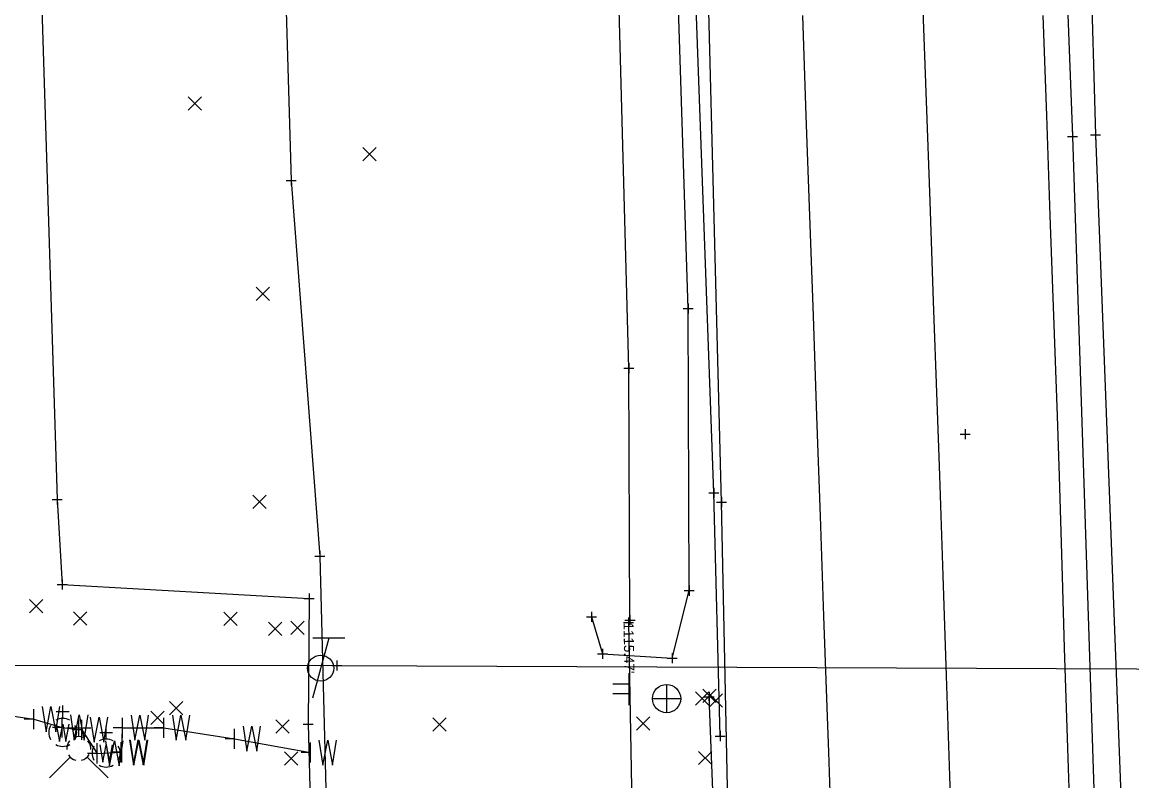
# Model space of a CAD drawing. Extents: x 146022 to 147632, y 437624 to 440659.
# Drawn here: x 146857.8 to 146968.6, y 438654.2 to 438729.9 of the extents above; entities that cross this region are included whole.
import ezdxf

# ---------------------------------------------------------------- set-up
doc = ezdxf.new("R2010")
doc.units = 0
for name, color, linetype in [('_CIVIL_CONSTRUCTION', 7, 'Continuous'), ('BR_P_Rail_Object', 7, 'Continuous'), ('DR_Channel', 7, 'Continuous'), ('DR_P_Underdrain', 7, 'Continuous'), ('DR_X_Storm_Sewer', 7, 'Continuous'), ('DT_X_Break_Line', 7, 'Continuous'), ('GE_P_Alignment_100_Distances', 7, 'Continuous'), ('PF_X_Ground_Line', 7, 'Continuous'), ('PV_P_Curb', 7, 'Continuous'), ('RD_P_Anchor_Assembly', 7, 'Continuous'), ('RD_P_Fence', 7, 'Continuous'), ('RD_P_GR_Lt_Replaced', 7, 'Continuous'), ('RD_P_GR_Rt', 7, 'Continuous'), ('SC_Scratch1', 7, 'Continuous'), ('SC_Scratch3', 7, 'Continuous'), ('SV_X_Control_Cells_Found', 7, 'Continuous'), ('UT_X_Overhead_Cable_TV', 7, 'Continuous'), ('UT_X_Overhead_Electric', 7, 'Continuous'), ('UT_X_Water', 7, 'Continuous')]:
    doc.layers.add(name, color=color, linetype=linetype)

msp = doc.modelspace()

# ---------------------------------------------------------------- linework, layer by layer
at = {"layer": '_CIVIL_CONSTRUCTION'}
for p, q in [((146874.38, 438721.14), (146875.71, 438722.48)), ((146874.38, 438722.48), (146875.71, 438721.14)), ((146891.83, 438716.1), (146893.16, 438717.43)), ((146891.83, 438717.43), (146893.16, 438716.1)), ((146881.16, 438702.15), (146882.49, 438703.48)), ((146881.16, 438703.48), (146882.49, 438702.15)), ((146880.84, 438681.37), (146882.18, 438682.7)), ((146880.84, 438682.7), (146882.18, 438681.37)), ((146858.55, 438670.97), (146859.88, 438672.31)), ((146858.55, 438672.31), (146859.88, 438670.97)), ((146862.93, 438669.75), (146864.26, 438671.08)), ((146862.93, 438671.08), (146864.26, 438669.75)), ((146877.93, 438669.69), (146879.27, 438671.02)), ((146877.93, 438671.02), (146879.27, 438669.69)), ((146882.42, 438668.71), (146883.75, 438670.05)), ((146882.42, 438670.05), (146883.75, 438668.71)), ((146884.64, 438668.79), (146885.97, 438670.13)), ((146884.64, 438670.13), (146885.97, 438668.79)), ((146925.01, 438661.74), (146926.34, 438663.08)), ((146925.01, 438663.08), (146926.34, 438661.74)), ((146925.74, 438662.02), (146927.08, 438663.36)), ((146925.74, 438663.36), (146927.08, 438662.02)), ((146872.51, 438660.77), (146873.84, 438662.11)), ((146872.51, 438662.11), (146873.84, 438660.77)), ((146926.37, 438661.54), (146927.71, 438662.87)), ((146926.37, 438662.87), (146927.71, 438661.54)), ((146870.67, 438659.82), (146872, 438661.15)), ((146870.67, 438661.15), (146872, 438659.82)), ((146883.15, 438658.97), (146884.48, 438660.3)), ((146883.15, 438660.3), (146884.48, 438658.97)), ((146898.81, 438659.14), (146900.15, 438660.47)), ((146898.81, 438660.47), (146900.15, 438659.14)), ((146919.12, 438659.24), (146920.46, 438660.58)), ((146919.12, 438660.58), (146920.46, 438659.24)), ((146884, 438655.76), (146885.33, 438657.09)), ((146884, 438657.09), (146885.33, 438655.76)), ((146925.32, 438655.81), (146926.65, 438657.14)), ((146925.32, 438657.14), (146926.65, 438655.81))]:
    msp.add_line(p, q, dxfattribs=at)
at = {"layer": 'BR_P_Rail_Object'}
msp.add_line((146857.9, 438790.96), (146861.31, 438682.29), dxfattribs=at)
msp.add_lwpolyline([(146861.31, 438682.29), (146861.8, 438673.8), (146886.47, 438672.39), (146886.37, 438659.85), (146886.65, 438648.5)], dxfattribs=at)
at = {"layer": 'DR_Channel'}
msp.add_lwpolyline([(146927.49, 438658.64), (146926.86, 438682.94), (146924.07, 438758.87), (146921.39, 438836.61)], dxfattribs=at)
at = {"layer": 'DR_P_Underdrain'}
msp.add_lwpolyline([(146928.3, 438613.34), (146926.37, 438662.58)], dxfattribs=at)
at = {"layer": 'DR_X_Storm_Sewer'}
msp.add_line((146918.33, 438670), (146920.42, 438556.95), dxfattribs=at)
at = {"layer": 'DT_X_Break_Line'}
for p, q in [((146918.36, 438664.95), (146918.36, 438661.75)), ((146918.36, 438663.83), (146916.76, 438663.83)), ((146918.36, 438663.35), (146918.36, 438663.35)), ((146918.36, 438662.87), (146916.76, 438662.87))]:
    msp.add_line(p, q, dxfattribs=at)
at = {"layer": 'GE_P_Alignment_100_Distances'}
msp.add_lwpolyline([(146750.22, 438665.83), (146889.21, 438665.72), (146992.98, 438665.29), (147118.65, 438665.14)], dxfattribs=at)
at = {"layer": 'PF_X_Ground_Line'}
for points in [[(146914.64, 438670.57), (146915.75, 438666.87), (146922.7, 438666.44), (146924.4, 438673.18), (146924.27, 438701.36), (146922.48, 438757.21), (146920.66, 438838.94), (146918.38, 438899.47), (146916.23, 438958.04), (146913.91, 439025.67), (146911.27, 439102.64)], [(146951.85, 439101), (146954.03, 439043.56), (146955.67, 438986.11), (146957.93, 438928.5), (146959.87, 438869.86), (146961.6, 438814.76), (146963.44, 438771.02), (146964.93, 438718.68), (146967.59, 438649.32)], [(146874.32, 439086.09), (146876.12, 439048.97), (146877.59, 438969.18), (146878.82, 438878.15), (146882.49, 438787.42), (146884.67, 438714.13), (146887.53, 438676.63), (146888.14, 438653.41), (146888.71, 438646.35), (146889.72, 438610.79)]]:
    msp.add_lwpolyline(points, dxfattribs=at)
at = {"layer": 'PV_P_Curb'}
msp.add_lwpolyline([(146947.67, 438732.04), (146948.03, 438722.05), (146948.39, 438712.05), (146948.75, 438702.06), (146949.11, 438692.07), (146949.38, 438684.67), (146949.71, 438674.68), (146950.03, 438664.68), (146950.36, 438654.69), (146950.69, 438644.69), (146951.02, 438634.7), (146951.35, 438624.7), (146951.68, 438614.71), (146952.01, 438604.72), (146952.33, 438594.72)], dxfattribs=at)
at = {"layer": 'RD_P_Anchor_Assembly'}
for p, q in [((146962.14, 438718.51), (146963.14, 438718.51)), ((146962.64, 438719.01), (146962.64, 438718.01)), ((146962.64, 438718.51), (146962.64, 438718.51)), ((146964.43, 438718.68), (146965.43, 438718.68)), ((146964.93, 438719.18), (146964.93, 438718.18)), ((146964.93, 438718.68), (146964.93, 438718.68)), ((146884.17, 438714.13), (146885.17, 438714.13)), ((146884.67, 438714.63), (146884.67, 438713.63)), ((146884.67, 438714.13), (146884.67, 438714.13)), ((146924.27, 438701.86), (146924.27, 438700.86)), ((146923.77, 438701.36), (146924.77, 438701.36)), ((146924.27, 438701.36), (146924.27, 438701.36)), ((146917.86, 438695.39), (146918.86, 438695.39)), ((146918.36, 438695.89), (146918.36, 438694.89)), ((146918.36, 438695.39), (146918.36, 438695.39)), ((146951.43, 438688.81), (146952.43, 438688.81)), ((146951.93, 438689.31), (146951.93, 438688.31)), ((146951.93, 438688.81), (146951.93, 438688.81)), ((146926.36, 438682.94), (146927.36, 438682.94)), ((146926.86, 438683.44), (146926.86, 438682.44)), ((146926.86, 438682.94), (146926.86, 438682.94)), ((146860.81, 438682.29), (146861.81, 438682.29)), ((146861.31, 438682.79), (146861.31, 438681.79)), ((146861.31, 438682.29), (146861.31, 438682.29)), ((146927.12, 438682.02), (146928.12, 438682.02)), ((146927.62, 438682.52), (146927.62, 438681.52)), ((146927.62, 438682.02), (146927.62, 438682.02)), ((146887.03, 438676.63), (146888.03, 438676.63)), ((146887.53, 438677.13), (146887.53, 438676.13)), ((146887.53, 438676.63), (146887.53, 438676.63)), ((146861.8, 438674.3), (146861.8, 438673.3)), ((146861.3, 438673.8), (146862.3, 438673.8)), ((146861.8, 438673.8), (146861.8, 438673.8)), ((146923.9, 438673.18), (146924.9, 438673.18)), ((146924.4, 438673.68), (146924.4, 438672.68)), ((146924.4, 438673.18), (146924.4, 438673.18)), ((146885.97, 438672.39), (146886.97, 438672.39)), ((146886.47, 438672.89), (146886.47, 438671.89)), ((146886.47, 438672.39), (146886.47, 438672.39)), ((146914.64, 438671.07), (146914.64, 438670.07)), ((146918.48, 438670.73), (146918.48, 438669.73)), ((146914.14, 438670.57), (146915.14, 438670.57)), ((146914.64, 438670.57), (146914.64, 438670.57)), ((146917.98, 438670.23), (146918.98, 438670.23)), ((146918.48, 438670.23), (146918.48, 438670.23)), ((146915.25, 438666.87), (146916.25, 438666.87)), ((146915.75, 438667.37), (146915.75, 438666.37)), ((146915.75, 438666.87), (146915.75, 438666.87)), ((146922.2, 438666.44), (146923.2, 438666.44)), ((146922.7, 438666.94), (146922.7, 438665.94)), ((146922.7, 438666.44), (146922.7, 438666.44)), ((146888.71, 438665.72), (146889.71, 438665.72)), ((146889.21, 438666.22), (146889.21, 438665.22)), ((146889.21, 438665.72), (146889.21, 438665.72)), ((146926.37, 438663.08), (146926.37, 438662.08)), ((146925.87, 438662.58), (146926.87, 438662.58)), ((146926.37, 438662.58), (146926.37, 438662.58)), ((146885.87, 438659.85), (146886.87, 438659.85)), ((146886.37, 438660.35), (146886.37, 438659.35)), ((146886.37, 438659.85), (146886.37, 438659.85)), ((146926.99, 438658.64), (146927.99, 438658.64)), ((146927.49, 438659.14), (146927.49, 438658.14)), ((146927.49, 438658.64), (146927.49, 438658.64))]:
    msp.add_line(p, q, dxfattribs=at)
at = {"layer": 'RD_P_Fence'}
msp.add_lwpolyline([(146918.48, 438670.23), (146918.36, 438695.39), (146916.78, 438754.68), (146913.53, 438840.01), (146911.11, 438897.17), (146908.49, 438958.23), (146907.32, 439024.66), (146905.15, 439103.64)], dxfattribs=at)
at = {"layer": 'RD_P_GR_Lt_Replaced'}
for points in [[(146929.27, 438613.38), (146928.66, 438631.37), (146927.62, 438682.02), (146925.57, 438760.71), (146923.55, 438837.34), (146921.1, 438899.44), (146919.06, 438958.23), (146916.57, 439025.76), (146914.01, 439102.63)], [(146949.53, 439101.12), (146951.47, 439043.06), (146953.42, 438986.87), (146955.3, 438928.33), (146957.21, 438869.74), (146959.24, 438814.61), (146960.64, 438770.62), (146962.64, 438718.51), (146964.89, 438649.27), (146966.6, 438595.69)]]:
    msp.add_lwpolyline(points, dxfattribs=at)
at = {"layer": 'RD_P_GR_Rt'}
for p, q in [((146858.98, 438659.35), (146858.98, 438661.35)), ((146862.5, 438661.07), (146861.23, 438661.07)), ((146861.87, 438660.43), (146861.87, 438661.7)), ((146858.98, 438660.35), (146858.03, 438660.35)), ((146861.8, 438658.52), (146861.8, 438660.52)), ((146863.47, 438658.61), (146863.47, 438660.33)), ((146863.77, 438658.3), (146863.77, 438660.3)), ((146866.2, 438658.37), (146866.2, 438659.64)), ((146867.85, 438658.5), (146867.85, 438660.5)), ((146871.96, 438658.5), (146871.96, 438660.5)), ((146861.8, 438659.52), (146860.85, 438659.52)), ((146861.87, 438659.03), (146861.87, 438659.03)), ((146864.67, 438659.47), (146862.27, 438659.47)), ((146863.77, 438659.3), (146862.82, 438659.3)), ((146866.84, 438659), (146865.57, 438659)), ((146867.85, 438659.5), (146866.9, 438659.5)), ((146871.96, 438659.5), (146871.01, 438659.5)), ((146879.02, 438657.4), (146879.02, 438659.4)), ((146865.3, 438655.94), (146865.3, 438657.94)), ((146867.7, 438656.05), (146867.7, 438658.05)), ((146867.76, 438656.02), (146867.76, 438658.02)), ((146879.02, 438658.4), (146878.07, 438658.4)), ((146886.6, 438656.02), (146886.6, 438658.02)), ((146862.62, 438656.56), (146860.54, 438654.48)), ((146863.47, 438657.41), (146863.47, 438657.41)), ((146863.47, 438657.41), (146863.47, 438657.41)), ((146864.31, 438656.56), (146866.39, 438654.48)), ((146865.3, 438656.94), (146864.35, 438656.94)), ((146866.2, 438656.97), (146866.2, 438656.97)), ((146867.7, 438657.05), (146866.74, 438657.05)), ((146867.76, 438657.02), (146866.81, 438657.02)), ((146886.6, 438657.02), (146885.65, 438657.02))]:
    msp.add_line(p, q, dxfattribs=at)
for points in [[(146859.83, 438661.6), (146860.2, 438659.1), (146860.69, 438661.6), (146861.19, 438659.1), (146861.58, 438661.6)], [(146862.64, 438660.77), (146863.02, 438658.27), (146863.51, 438660.77), (146864, 438658.27), (146864.4, 438660.77)], [(146868.69, 438660.75), (146869.07, 438658.25), (146869.56, 438660.75), (146870.05, 438658.25), (146870.44, 438660.75)], [(146872.81, 438660.75), (146873.18, 438658.25), (146873.67, 438660.75), (146874.16, 438658.25), (146874.56, 438660.75)], [(146861.23, 438659.85), (146861.55, 438658.13), (146861.87, 438659.85), (146862.19, 438658.13), (146862.5, 438659.85)], [(146864.62, 438660.55), (146864.99, 438658.05), (146865.49, 438660.55), (146865.98, 438658.05), (146866.37, 438660.55)], [(146879.87, 438659.65), (146880.24, 438657.15), (146880.74, 438659.65), (146881.23, 438657.15), (146881.62, 438659.65)], [(146865.57, 438657.79), (146865.88, 438656.06), (146866.2, 438657.79), (146866.52, 438656.06), (146866.84, 438657.79)], [(146866.15, 438658.19), (146866.52, 438655.69), (146867.02, 438658.19), (146867.51, 438655.69), (146867.9, 438658.19)], [(146868.54, 438658.3), (146868.92, 438655.8), (146869.41, 438658.3), (146869.9, 438655.8), (146870.29, 438658.3)], [(146868.6, 438658.27), (146868.98, 438655.77), (146869.47, 438658.27), (146869.96, 438655.77), (146870.36, 438658.27)], [(146887.44, 438658.27), (146887.82, 438655.77), (146888.31, 438658.27), (146888.8, 438655.77), (146889.2, 438658.27)]]:
    msp.add_lwpolyline(points, dxfattribs=at)
for centre, radius, start, end in [((146861.87, 438659.03), 1.4, 150.0184, 209.9816), ((146861.87, 438659.03), 1.4, 60.0184, 120.0157), ((146861.87, 438659.03), 1.4, 330.0184, 29.9816), ((146863.47, 438657.41), 1.2, 68.1395, 112.038), ((146861.87, 438659.03), 1.4, 239.9843, 299.9816), ((146863.47, 438657.41), 1.2, 140.021, 184.0629), ((146863.47, 438657.41), 1.2, 356.0165, 39.9889), ((146866.2, 438656.97), 1.4, 150.0184, 209.9816), ((146866.2, 438656.97), 1.4, 60.0184, 120.0157), ((146866.2, 438656.97), 1.4, 330.0184, 29.9816), ((146863.47, 438657.41), 1.2, 211.8788, 255.8479), ((146863.47, 438657.41), 1.2, 283.8239, 329.9097), ((146866.2, 438656.97), 1.4, 239.9843, 299.9816)]:
    msp.add_arc(centre, radius, start, end, dxfattribs=at)
at = {"layer": 'SC_Scratch3'}
for points in [[(146940.4, 438597.1), (146940.05, 438607.1), (146939.71, 438617.09), (146939.36, 438627.09), (146939.01, 438637.08), (146938.66, 438647.07), (146938.31, 438657.07), (146938.19, 438660.63), (146937.83, 438670.62), (146937.48, 438680.62), (146937.13, 438690.61), (146936.78, 438700.61), (146936.43, 438710.6), (146936.07, 438720.59), (146935.72, 438730.59)], [(146959.68, 438730.61), (146960.04, 438720.62), (146960.39, 438710.63), (146960.75, 438700.63), (146961.11, 438690.64), (146961.32, 438684.6), (146961.61, 438674.6), (146961.82, 438667.46), (146962.14, 438657.47), (146962.47, 438647.47), (146962.8, 438637.48), (146963.12, 438627.48), (146963.45, 438617.49), (146963.78, 438607.49), (146964.1, 438597.5)]]:
    msp.add_lwpolyline(points, dxfattribs=at)
at = {"layer": 'SV_X_Control_Cells_Found'}
for p, q in [((146922.13, 438663.81), (146922.13, 438660.99)), ((146920.73, 438662.4), (146923.54, 438662.4))]:
    msp.add_line(p, q, dxfattribs=at)
msp.add_circle((146922.13, 438662.4), 1.41, dxfattribs=at)
at = {"layer": 'UT_X_Overhead_Cable_TV'}
for p, q in [((146888.42, 438668.44), (146886.81, 438662.44)), ((146890.02, 438668.44), (146886.82, 438668.44))]:
    msp.add_line(p, q, dxfattribs=at)
msp.add_circle((146887.61, 438665.44), 1.3, dxfattribs=at)
at = {"layer": 'UT_X_Overhead_Electric'}
for p, q in [((146917.83, 438670), (146918.83, 438670)), ((146918.33, 438670.5), (146918.33, 438669.5)), ((146918.33, 438670), (146918.33, 438670))]:
    msp.add_line(p, q, dxfattribs=at)
at = {"layer": 'UT_X_Water'}
msp.add_lwpolyline([(146845.7, 438661.46), (146852.1, 438661.4), (146858.98, 438660.35), (146861.8, 438659.52), (146863.77, 438659.3), (146865.3, 438656.94), (146867.7, 438657.05), (146867.76, 438657.02), (146867.85, 438659.5), (146871.96, 438659.5), (146879.02, 438658.4), (146886.6, 438657.02)], dxfattribs=at)

# ---------------------------------------------------------------- texts
at = {"layer": 'SC_Scratch1'}
msp.add_text("1115.47'", height=1, rotation=271.0581, dxfattribs=at).set_placement((146917.83, 438669.99))

doc.saveas('drawing.dxf')
